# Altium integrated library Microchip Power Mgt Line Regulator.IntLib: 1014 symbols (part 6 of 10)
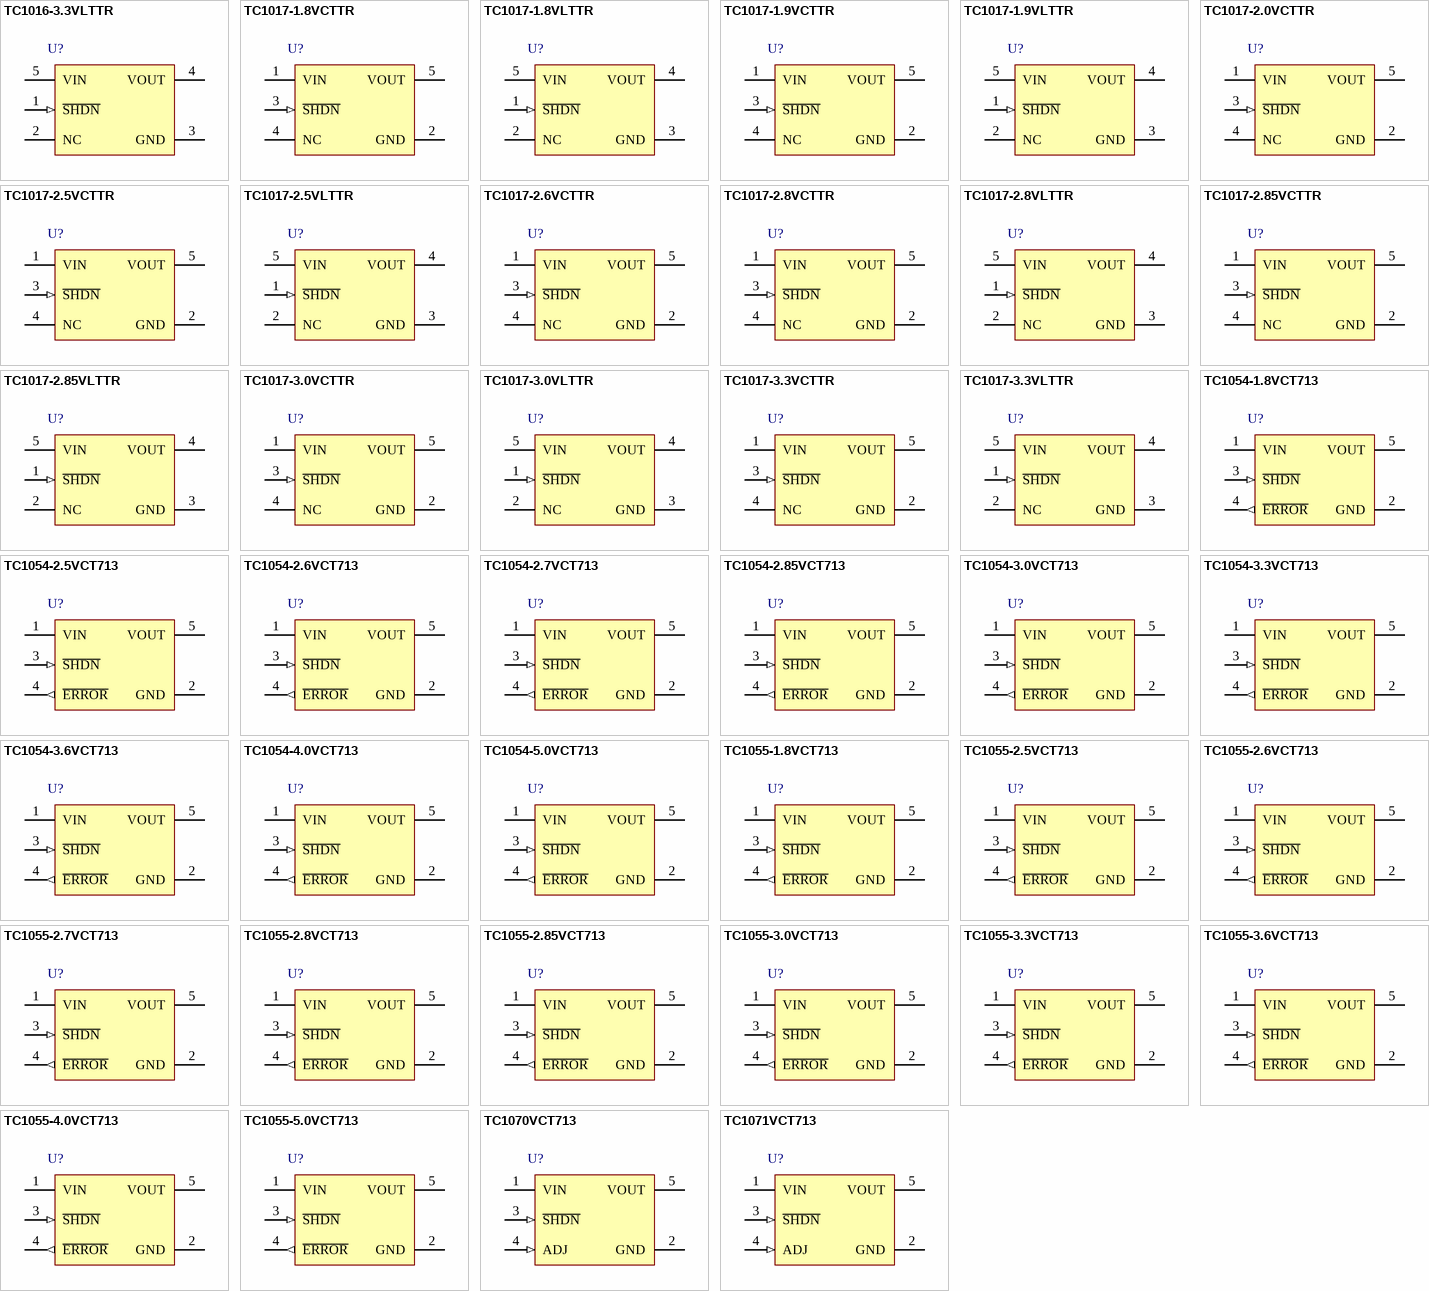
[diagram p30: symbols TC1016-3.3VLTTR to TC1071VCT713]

## TC1017-2.6VCTTR
designator U?
150 mA, Tiny CMOS LDO with Shutdown, 5-Pin SOT-23, Extended Temperature, Tape and Reel
footprint SOT-23-CT5_N (SOT23, 5-Leads, Body 2.9x1.6mm, Pitch 0.95mm, Lead Span 2.7mm, IPC Medium Density)
footprint SOT-23-CT5_L (SOT23, 5-Leads, Body 2.9x1.6mm, Pitch 0.95mm, Lead Span 2.7mm, IPC High Density)
footprint SOT-23-CT5_M (SOT23, 5-Leads, Body 2.9x1.6mm, Pitch 0.95mm, Lead Span 2.7mm, IPC Low Density)
pins: 1 VIN (power), 2 GND (power), 3 ~{SHDN} (in), 4 NC, 5 VOUT (power)

## TC1017-2.8VCTTR
designator U?
150 mA, Tiny CMOS LDO with Shutdown, 5-Pin SOT-23, Extended Temperature, Tape and Reel
footprint SOT-23-CT5_N (SOT23, 5-Leads, Body 2.9x1.6mm, Pitch 0.95mm, Lead Span 2.7mm, IPC Medium Density)
footprint SOT-23-CT5_L (SOT23, 5-Leads, Body 2.9x1.6mm, Pitch 0.95mm, Lead Span 2.7mm, IPC High Density)
footprint SOT-23-CT5_M (SOT23, 5-Leads, Body 2.9x1.6mm, Pitch 0.95mm, Lead Span 2.7mm, IPC Low Density)
pins: 1 VIN (power), 2 GND (power), 3 ~{SHDN} (in), 4 NC, 5 VOUT (power)

## TC1017-2.8VLTTR
designator U?
150 mA, Tiny CMOS LDO with Shutdown, 5-Pin SC-70, Extended Temperature, Tape and Reel
footprint SC70-LT5_N (SOT353, 5-Leads, Body 2x1.3mm, Pitch 0.65mm, Lead Span 2.1mm, IPC Medium Density)
footprint SC70-LT5_L (SOT353, 5-Leads, Body 2x1.3mm, Pitch 0.65mm, Lead Span 2.1mm, IPC High Density)
footprint SC70-LT5_M (SOT353, 5-Leads, Body 2x1.3mm, Pitch 0.65mm, Lead Span 2.1mm, IPC Low Density)
pins: 1 ~{SHDN} (in), 2 NC, 3 GND (power), 4 VOUT (power), 5 VIN (power)

## TC1017-2.85VCTTR
designator U?
150 mA, Tiny CMOS LDO with Shutdown, 5-Pin SOT-23, Extended Temperature, Tape and Reel
footprint SOT-23-CT5_N (SOT23, 5-Leads, Body 2.9x1.6mm, Pitch 0.95mm, Lead Span 2.7mm, IPC Medium Density)
footprint SOT-23-CT5_L (SOT23, 5-Leads, Body 2.9x1.6mm, Pitch 0.95mm, Lead Span 2.7mm, IPC High Density)
footprint SOT-23-CT5_M (SOT23, 5-Leads, Body 2.9x1.6mm, Pitch 0.95mm, Lead Span 2.7mm, IPC Low Density)
pins: 1 VIN (power), 2 GND (power), 3 ~{SHDN} (in), 4 NC, 5 VOUT (power)

## TC1017-2.85VLTTR
designator U?
150 mA, Tiny CMOS LDO with Shutdown, 5-Pin SC-70, Extended Temperature, Tape and Reel
footprint SC70-LT5_N (SOT353, 5-Leads, Body 2x1.3mm, Pitch 0.65mm, Lead Span 2.1mm, IPC Medium Density)
footprint SC70-LT5_L (SOT353, 5-Leads, Body 2x1.3mm, Pitch 0.65mm, Lead Span 2.1mm, IPC High Density)
footprint SC70-LT5_M (SOT353, 5-Leads, Body 2x1.3mm, Pitch 0.65mm, Lead Span 2.1mm, IPC Low Density)
pins: 1 ~{SHDN} (in), 2 NC, 3 GND (power), 4 VOUT (power), 5 VIN (power)

## TC1017-3.0VCTTR
designator U?
150 mA, Tiny CMOS LDO with Shutdown, 5-Pin SOT-23, Extended Temperature, Tape and Reel
footprint SOT-23-CT5_N (SOT23, 5-Leads, Body 2.9x1.6mm, Pitch 0.95mm, Lead Span 2.7mm, IPC Medium Density)
footprint SOT-23-CT5_L (SOT23, 5-Leads, Body 2.9x1.6mm, Pitch 0.95mm, Lead Span 2.7mm, IPC High Density)
footprint SOT-23-CT5_M (SOT23, 5-Leads, Body 2.9x1.6mm, Pitch 0.95mm, Lead Span 2.7mm, IPC Low Density)
pins: 1 VIN (power), 2 GND (power), 3 ~{SHDN} (in), 4 NC, 5 VOUT (power)

## TC1017-3.0VLTTR
designator U?
150 mA, Tiny CMOS LDO with Shutdown, 5-Pin SC-70, Extended Temperature, Tape and Reel
footprint SC70-LT5_N (SOT353, 5-Leads, Body 2x1.3mm, Pitch 0.65mm, Lead Span 2.1mm, IPC Medium Density)
footprint SC70-LT5_L (SOT353, 5-Leads, Body 2x1.3mm, Pitch 0.65mm, Lead Span 2.1mm, IPC High Density)
footprint SC70-LT5_M (SOT353, 5-Leads, Body 2x1.3mm, Pitch 0.65mm, Lead Span 2.1mm, IPC Low Density)
pins: 1 ~{SHDN} (in), 2 NC, 3 GND (power), 4 VOUT (power), 5 VIN (power)

## TC1017-3.3VCTTR
designator U?
150 mA, Tiny CMOS LDO with Shutdown, 5-Pin SOT-23, Extended Temperature, Tape and Reel
footprint SOT-23-CT5_N (SOT23, 5-Leads, Body 2.9x1.6mm, Pitch 0.95mm, Lead Span 2.7mm, IPC Medium Density)
footprint SOT-23-CT5_L (SOT23, 5-Leads, Body 2.9x1.6mm, Pitch 0.95mm, Lead Span 2.7mm, IPC High Density)
footprint SOT-23-CT5_M (SOT23, 5-Leads, Body 2.9x1.6mm, Pitch 0.95mm, Lead Span 2.7mm, IPC Low Density)
pins: 1 VIN (power), 2 GND (power), 3 ~{SHDN} (in), 4 NC, 5 VOUT (power)

## TC1017-3.3VLTTR
designator U?
150 mA, Tiny CMOS LDO with Shutdown, 5-Pin SC-70, Extended Temperature, Tape and Reel
footprint SC70-LT5_N (SOT353, 5-Leads, Body 2x1.3mm, Pitch 0.65mm, Lead Span 2.1mm, IPC Medium Density)
footprint SC70-LT5_L (SOT353, 5-Leads, Body 2x1.3mm, Pitch 0.65mm, Lead Span 2.1mm, IPC High Density)
footprint SC70-LT5_M (SOT353, 5-Leads, Body 2x1.3mm, Pitch 0.65mm, Lead Span 2.1mm, IPC Low Density)
pins: 1 ~{SHDN} (in), 2 NC, 3 GND (power), 4 VOUT (power), 5 VIN (power)

## TC1054-1.8VCT713
designator U?
50 mA, 100 mA and 150 mA CMOS LDOs with Shutdown and Active-Low Error Output, 5-Pin SOT-23, Extended Temperature, Tape and Reel
footprint SOT-23-CT5_N (SOT23, 5-Leads, Body 2.9x1.6mm, Pitch 0.95mm, Lead Span 2.7mm, IPC Medium Density)
footprint SOT-23-CT5_L (SOT23, 5-Leads, Body 2.9x1.6mm, Pitch 0.95mm, Lead Span 2.7mm, IPC High Density)
footprint SOT-23-CT5_M (SOT23, 5-Leads, Body 2.9x1.6mm, Pitch 0.95mm, Lead Span 2.7mm, IPC Low Density)
pins: 1 VIN (power), 2 GND (power), 3 ~{SHDN} (in), 4 ~{ERROR} (out), 5 VOUT (power)

## TC1054-2.5VCT713
designator U?
50 mA, 100 mA and 150 mA CMOS LDOs with Shutdown and Active-Low Error Output, 5-Pin SOT-23, Extended Temperature, Tape and Reel
footprint SOT-23-CT5_N (SOT23, 5-Leads, Body 2.9x1.6mm, Pitch 0.95mm, Lead Span 2.7mm, IPC Medium Density)
footprint SOT-23-CT5_L (SOT23, 5-Leads, Body 2.9x1.6mm, Pitch 0.95mm, Lead Span 2.7mm, IPC High Density)
footprint SOT-23-CT5_M (SOT23, 5-Leads, Body 2.9x1.6mm, Pitch 0.95mm, Lead Span 2.7mm, IPC Low Density)
pins: 1 VIN (power), 2 GND (power), 3 ~{SHDN} (in), 4 ~{ERROR} (out), 5 VOUT (power)

## TC1054-2.6VCT713
designator U?
50 mA, 100 mA and 150 mA CMOS LDOs with Shutdown and Active-Low Error Output, 5-Pin SOT-23, Extended Temperature, Tape and Reel
footprint SOT-23-CT5_N (SOT23, 5-Leads, Body 2.9x1.6mm, Pitch 0.95mm, Lead Span 2.7mm, IPC Medium Density)
footprint SOT-23-CT5_L (SOT23, 5-Leads, Body 2.9x1.6mm, Pitch 0.95mm, Lead Span 2.7mm, IPC High Density)
footprint SOT-23-CT5_M (SOT23, 5-Leads, Body 2.9x1.6mm, Pitch 0.95mm, Lead Span 2.7mm, IPC Low Density)
pins: 1 VIN (power), 2 GND (power), 3 ~{SHDN} (in), 4 ~{ERROR} (out), 5 VOUT (power)

## TC1054-2.7VCT713
designator U?
50 mA, 100 mA and 150 mA CMOS LDOs with Shutdown and Active-Low Error Output, 5-Pin SOT-23, Extended Temperature, Tape and Reel
footprint SOT-23-CT5_N (SOT23, 5-Leads, Body 2.9x1.6mm, Pitch 0.95mm, Lead Span 2.7mm, IPC Medium Density)
footprint SOT-23-CT5_L (SOT23, 5-Leads, Body 2.9x1.6mm, Pitch 0.95mm, Lead Span 2.7mm, IPC High Density)
footprint SOT-23-CT5_M (SOT23, 5-Leads, Body 2.9x1.6mm, Pitch 0.95mm, Lead Span 2.7mm, IPC Low Density)
pins: 1 VIN (power), 2 GND (power), 3 ~{SHDN} (in), 4 ~{ERROR} (out), 5 VOUT (power)

## TC1054-2.85VCT713
designator U?
50 mA, 100 mA and 150 mA CMOS LDOs with Shutdown and Active-Low Error Output, 5-Pin SOT-23, Extended Temperature, Tape and Reel
footprint SOT-23-CT5_N (SOT23, 5-Leads, Body 2.9x1.6mm, Pitch 0.95mm, Lead Span 2.7mm, IPC Medium Density)
footprint SOT-23-CT5_L (SOT23, 5-Leads, Body 2.9x1.6mm, Pitch 0.95mm, Lead Span 2.7mm, IPC High Density)
footprint SOT-23-CT5_M (SOT23, 5-Leads, Body 2.9x1.6mm, Pitch 0.95mm, Lead Span 2.7mm, IPC Low Density)
pins: 1 VIN (power), 2 GND (power), 3 ~{SHDN} (in), 4 ~{ERROR} (out), 5 VOUT (power)

## TC1054-3.0VCT713
designator U?
50 mA, 100 mA and 150 mA CMOS LDOs with Shutdown and Active-Low Error Output, 5-Pin SOT-23, Extended Temperature, Tape and Reel
footprint SOT-23-CT5_N (SOT23, 5-Leads, Body 2.9x1.6mm, Pitch 0.95mm, Lead Span 2.7mm, IPC Medium Density)
footprint SOT-23-CT5_L (SOT23, 5-Leads, Body 2.9x1.6mm, Pitch 0.95mm, Lead Span 2.7mm, IPC High Density)
footprint SOT-23-CT5_M (SOT23, 5-Leads, Body 2.9x1.6mm, Pitch 0.95mm, Lead Span 2.7mm, IPC Low Density)
pins: 1 VIN (power), 2 GND (power), 3 ~{SHDN} (in), 4 ~{ERROR} (out), 5 VOUT (power)

## TC1054-3.3VCT713
designator U?
50 mA, 100 mA and 150 mA CMOS LDOs with Shutdown and Active-Low Error Output, 5-Pin SOT-23, Extended Temperature, Tape and Reel
footprint SOT-23-CT5_N (SOT23, 5-Leads, Body 2.9x1.6mm, Pitch 0.95mm, Lead Span 2.7mm, IPC Medium Density)
footprint SOT-23-CT5_L (SOT23, 5-Leads, Body 2.9x1.6mm, Pitch 0.95mm, Lead Span 2.7mm, IPC High Density)
footprint SOT-23-CT5_M (SOT23, 5-Leads, Body 2.9x1.6mm, Pitch 0.95mm, Lead Span 2.7mm, IPC Low Density)
pins: 1 VIN (power), 2 GND (power), 3 ~{SHDN} (in), 4 ~{ERROR} (out), 5 VOUT (power)

## TC1054-3.6VCT713
designator U?
50 mA, 100 mA and 150 mA CMOS LDOs with Shutdown and Active-Low Error Output, 5-Pin SOT-23, Extended Temperature, Tape and Reel
footprint SOT-23-CT5_N (SOT23, 5-Leads, Body 2.9x1.6mm, Pitch 0.95mm, Lead Span 2.7mm, IPC Medium Density)
footprint SOT-23-CT5_L (SOT23, 5-Leads, Body 2.9x1.6mm, Pitch 0.95mm, Lead Span 2.7mm, IPC High Density)
footprint SOT-23-CT5_M (SOT23, 5-Leads, Body 2.9x1.6mm, Pitch 0.95mm, Lead Span 2.7mm, IPC Low Density)
pins: 1 VIN (power), 2 GND (power), 3 ~{SHDN} (in), 4 ~{ERROR} (out), 5 VOUT (power)

## TC1054-4.0VCT713
designator U?
50 mA, 100 mA and 150 mA CMOS LDOs with Shutdown and Active-Low Error Output, 5-Pin SOT-23, Extended Temperature, Tape and Reel
footprint SOT-23-CT5_N (SOT23, 5-Leads, Body 2.9x1.6mm, Pitch 0.95mm, Lead Span 2.7mm, IPC Medium Density)
footprint SOT-23-CT5_L (SOT23, 5-Leads, Body 2.9x1.6mm, Pitch 0.95mm, Lead Span 2.7mm, IPC High Density)
footprint SOT-23-CT5_M (SOT23, 5-Leads, Body 2.9x1.6mm, Pitch 0.95mm, Lead Span 2.7mm, IPC Low Density)
pins: 1 VIN (power), 2 GND (power), 3 ~{SHDN} (in), 4 ~{ERROR} (out), 5 VOUT (power)

## TC1054-5.0VCT713
designator U?
50 mA, 100 mA and 150 mA CMOS LDOs with Shutdown and Active-Low Error Output, 5-Pin SOT-23, Extended Temperature, Tape and Reel
footprint SOT-23-CT5_N (SOT23, 5-Leads, Body 2.9x1.6mm, Pitch 0.95mm, Lead Span 2.7mm, IPC Medium Density)
footprint SOT-23-CT5_L (SOT23, 5-Leads, Body 2.9x1.6mm, Pitch 0.95mm, Lead Span 2.7mm, IPC High Density)
footprint SOT-23-CT5_M (SOT23, 5-Leads, Body 2.9x1.6mm, Pitch 0.95mm, Lead Span 2.7mm, IPC Low Density)
pins: 1 VIN (power), 2 GND (power), 3 ~{SHDN} (in), 4 ~{ERROR} (out), 5 VOUT (power)

## TC1055-1.8VCT713
designator U?
50 mA, 100 mA and 150 mA CMOS LDOs with Shutdown and Active-Low Error Output, 5-Pin SOT-23, Extended Temperature, Tape and Reel
footprint SOT-23-CT5_N (SOT23, 5-Leads, Body 2.9x1.6mm, Pitch 0.95mm, Lead Span 2.7mm, IPC Medium Density)
footprint SOT-23-CT5_L (SOT23, 5-Leads, Body 2.9x1.6mm, Pitch 0.95mm, Lead Span 2.7mm, IPC High Density)
footprint SOT-23-CT5_M (SOT23, 5-Leads, Body 2.9x1.6mm, Pitch 0.95mm, Lead Span 2.7mm, IPC Low Density)
pins: 1 VIN (power), 2 GND (power), 3 ~{SHDN} (in), 4 ~{ERROR} (out), 5 VOUT (power)

## TC1055-2.5VCT713
designator U?
50 mA, 100 mA and 150 mA CMOS LDOs with Shutdown and Active-Low Error Output, 5-Pin SOT-23, Extended Temperature, Tape and Reel
footprint SOT-23-CT5_N (SOT23, 5-Leads, Body 2.9x1.6mm, Pitch 0.95mm, Lead Span 2.7mm, IPC Medium Density)
footprint SOT-23-CT5_L (SOT23, 5-Leads, Body 2.9x1.6mm, Pitch 0.95mm, Lead Span 2.7mm, IPC High Density)
footprint SOT-23-CT5_M (SOT23, 5-Leads, Body 2.9x1.6mm, Pitch 0.95mm, Lead Span 2.7mm, IPC Low Density)
pins: 1 VIN (power), 2 GND (power), 3 ~{SHDN} (in), 4 ~{ERROR} (out), 5 VOUT (power)

## TC1055-2.6VCT713
designator U?
50 mA, 100 mA and 150 mA CMOS LDOs with Shutdown and Active-Low Error Output, 5-Pin SOT-23, Extended Temperature, Tape and Reel
footprint SOT-23-CT5_N (SOT23, 5-Leads, Body 2.9x1.6mm, Pitch 0.95mm, Lead Span 2.7mm, IPC Medium Density)
footprint SOT-23-CT5_L (SOT23, 5-Leads, Body 2.9x1.6mm, Pitch 0.95mm, Lead Span 2.7mm, IPC High Density)
footprint SOT-23-CT5_M (SOT23, 5-Leads, Body 2.9x1.6mm, Pitch 0.95mm, Lead Span 2.7mm, IPC Low Density)
pins: 1 VIN (power), 2 GND (power), 3 ~{SHDN} (in), 4 ~{ERROR} (out), 5 VOUT (power)

## TC1055-2.7VCT713
designator U?
50 mA, 100 mA and 150 mA CMOS LDOs with Shutdown and Active-Low Error Output, 5-Pin SOT-23, Extended Temperature, Tape and Reel
footprint SOT-23-CT5_N (SOT23, 5-Leads, Body 2.9x1.6mm, Pitch 0.95mm, Lead Span 2.7mm, IPC Medium Density)
footprint SOT-23-CT5_L (SOT23, 5-Leads, Body 2.9x1.6mm, Pitch 0.95mm, Lead Span 2.7mm, IPC High Density)
footprint SOT-23-CT5_M (SOT23, 5-Leads, Body 2.9x1.6mm, Pitch 0.95mm, Lead Span 2.7mm, IPC Low Density)
pins: 1 VIN (power), 2 GND (power), 3 ~{SHDN} (in), 4 ~{ERROR} (out), 5 VOUT (power)

## TC1055-2.8VCT713
designator U?
50 mA, 100 mA and 150 mA CMOS LDOs with Shutdown and Active-Low Error Output, 5-Pin SOT-23, Extended Temperature, Tape and Reel
footprint SOT-23-CT5_N (SOT23, 5-Leads, Body 2.9x1.6mm, Pitch 0.95mm, Lead Span 2.7mm, IPC Medium Density)
footprint SOT-23-CT5_L (SOT23, 5-Leads, Body 2.9x1.6mm, Pitch 0.95mm, Lead Span 2.7mm, IPC High Density)
footprint SOT-23-CT5_M (SOT23, 5-Leads, Body 2.9x1.6mm, Pitch 0.95mm, Lead Span 2.7mm, IPC Low Density)
pins: 1 VIN (power), 2 GND (power), 3 ~{SHDN} (in), 4 ~{ERROR} (out), 5 VOUT (power)

## TC1055-2.85VCT713
designator U?
50 mA, 100 mA and 150 mA CMOS LDOs with Shutdown and Active-Low Error Output, 5-Pin SOT-23, Extended Temperature, Tape and Reel
footprint SOT-23-CT5_N (SOT23, 5-Leads, Body 2.9x1.6mm, Pitch 0.95mm, Lead Span 2.7mm, IPC Medium Density)
footprint SOT-23-CT5_L (SOT23, 5-Leads, Body 2.9x1.6mm, Pitch 0.95mm, Lead Span 2.7mm, IPC High Density)
footprint SOT-23-CT5_M (SOT23, 5-Leads, Body 2.9x1.6mm, Pitch 0.95mm, Lead Span 2.7mm, IPC Low Density)
pins: 1 VIN (power), 2 GND (power), 3 ~{SHDN} (in), 4 ~{ERROR} (out), 5 VOUT (power)

## TC1055-3.0VCT713
designator U?
50 mA, 100 mA and 150 mA CMOS LDOs with Shutdown and Active-Low Error Output, 5-Pin SOT-23, Extended Temperature, Tape and Reel
footprint SOT-23-CT5_N (SOT23, 5-Leads, Body 2.9x1.6mm, Pitch 0.95mm, Lead Span 2.7mm, IPC Medium Density)
footprint SOT-23-CT5_L (SOT23, 5-Leads, Body 2.9x1.6mm, Pitch 0.95mm, Lead Span 2.7mm, IPC High Density)
footprint SOT-23-CT5_M (SOT23, 5-Leads, Body 2.9x1.6mm, Pitch 0.95mm, Lead Span 2.7mm, IPC Low Density)
pins: 1 VIN (power), 2 GND (power), 3 ~{SHDN} (in), 4 ~{ERROR} (out), 5 VOUT (power)

## TC1055-3.3VCT713
designator U?
50 mA, 100 mA and 150 mA CMOS LDOs with Shutdown and Active-Low Error Output, 5-Pin SOT-23, Extended Temperature, Tape and Reel
footprint SOT-23-CT5_N (SOT23, 5-Leads, Body 2.9x1.6mm, Pitch 0.95mm, Lead Span 2.7mm, IPC Medium Density)
footprint SOT-23-CT5_L (SOT23, 5-Leads, Body 2.9x1.6mm, Pitch 0.95mm, Lead Span 2.7mm, IPC High Density)
footprint SOT-23-CT5_M (SOT23, 5-Leads, Body 2.9x1.6mm, Pitch 0.95mm, Lead Span 2.7mm, IPC Low Density)
pins: 1 VIN (power), 2 GND (power), 3 ~{SHDN} (in), 4 ~{ERROR} (out), 5 VOUT (power)

## TC1055-3.6VCT713
designator U?
50 mA, 100 mA and 150 mA CMOS LDOs with Shutdown and Active-Low Error Output, 5-Pin SOT-23, Extended Temperature, Tape and Reel
footprint SOT-23-CT5_N (SOT23, 5-Leads, Body 2.9x1.6mm, Pitch 0.95mm, Lead Span 2.7mm, IPC Medium Density)
footprint SOT-23-CT5_L (SOT23, 5-Leads, Body 2.9x1.6mm, Pitch 0.95mm, Lead Span 2.7mm, IPC High Density)
footprint SOT-23-CT5_M (SOT23, 5-Leads, Body 2.9x1.6mm, Pitch 0.95mm, Lead Span 2.7mm, IPC Low Density)
pins: 1 VIN (power), 2 GND (power), 3 ~{SHDN} (in), 4 ~{ERROR} (out), 5 VOUT (power)

## TC1055-4.0VCT713
designator U?
50 mA, 100 mA and 150 mA CMOS LDOs with Shutdown and Active-Low Error Output, 5-Pin SOT-23, Extended Temperature, Tape and Reel
footprint SOT-23-CT5_N (SOT23, 5-Leads, Body 2.9x1.6mm, Pitch 0.95mm, Lead Span 2.7mm, IPC Medium Density)
footprint SOT-23-CT5_L (SOT23, 5-Leads, Body 2.9x1.6mm, Pitch 0.95mm, Lead Span 2.7mm, IPC High Density)
footprint SOT-23-CT5_M (SOT23, 5-Leads, Body 2.9x1.6mm, Pitch 0.95mm, Lead Span 2.7mm, IPC Low Density)
pins: 1 VIN (power), 2 GND (power), 3 ~{SHDN} (in), 4 ~{ERROR} (out), 5 VOUT (power)

## TC1055-5.0VCT713
designator U?
50 mA, 100 mA and 150 mA CMOS LDOs with Shutdown and Active-Low Error Output, 5-Pin SOT-23, Extended Temperature, Tape and Reel
footprint SOT-23-CT5_N (SOT23, 5-Leads, Body 2.9x1.6mm, Pitch 0.95mm, Lead Span 2.7mm, IPC Medium Density)
footprint SOT-23-CT5_L (SOT23, 5-Leads, Body 2.9x1.6mm, Pitch 0.95mm, Lead Span 2.7mm, IPC High Density)
footprint SOT-23-CT5_M (SOT23, 5-Leads, Body 2.9x1.6mm, Pitch 0.95mm, Lead Span 2.7mm, IPC Low Density)
pins: 1 VIN (power), 2 GND (power), 3 ~{SHDN} (in), 4 ~{ERROR} (out), 5 VOUT (power)

## TC1070VCT713
designator U?
50mA, 100mA and 150mA Adjustable CMOS LDOs with Shutdown, 5-Pin SOT-23, Extended Temperature, Tape and Reel
footprint SOT-23-CT5_N (SOT23, 5-Leads, Body 2.9x1.6mm, Pitch 0.95mm, Lead Span 2.7mm, IPC Medium Density)
footprint SOT-23-CT5_L (SOT23, 5-Leads, Body 2.9x1.6mm, Pitch 0.95mm, Lead Span 2.7mm, IPC High Density)
footprint SOT-23-CT5_M (SOT23, 5-Leads, Body 2.9x1.6mm, Pitch 0.95mm, Lead Span 2.7mm, IPC Low Density)
pins: 1 VIN (power), 2 GND (power), 3 ~{SHDN} (in), 4 ADJ (in), 5 VOUT (power)

## TC1071VCT713
designator U?
50mA, 100mA and 150mA Adjustable CMOS LDOs with Shutdown, 5-Pin SOT-23, Extended Temperature, Tape and Reel
footprint SOT-23-CT5_N (SOT23, 5-Leads, Body 2.9x1.6mm, Pitch 0.95mm, Lead Span 2.7mm, IPC Medium Density)
footprint SOT-23-CT5_L (SOT23, 5-Leads, Body 2.9x1.6mm, Pitch 0.95mm, Lead Span 2.7mm, IPC High Density)
footprint SOT-23-CT5_M (SOT23, 5-Leads, Body 2.9x1.6mm, Pitch 0.95mm, Lead Span 2.7mm, IPC Low Density)
pins: 1 VIN (power), 2 GND (power), 3 ~{SHDN} (in), 4 ADJ (in), 5 VOUT (power)

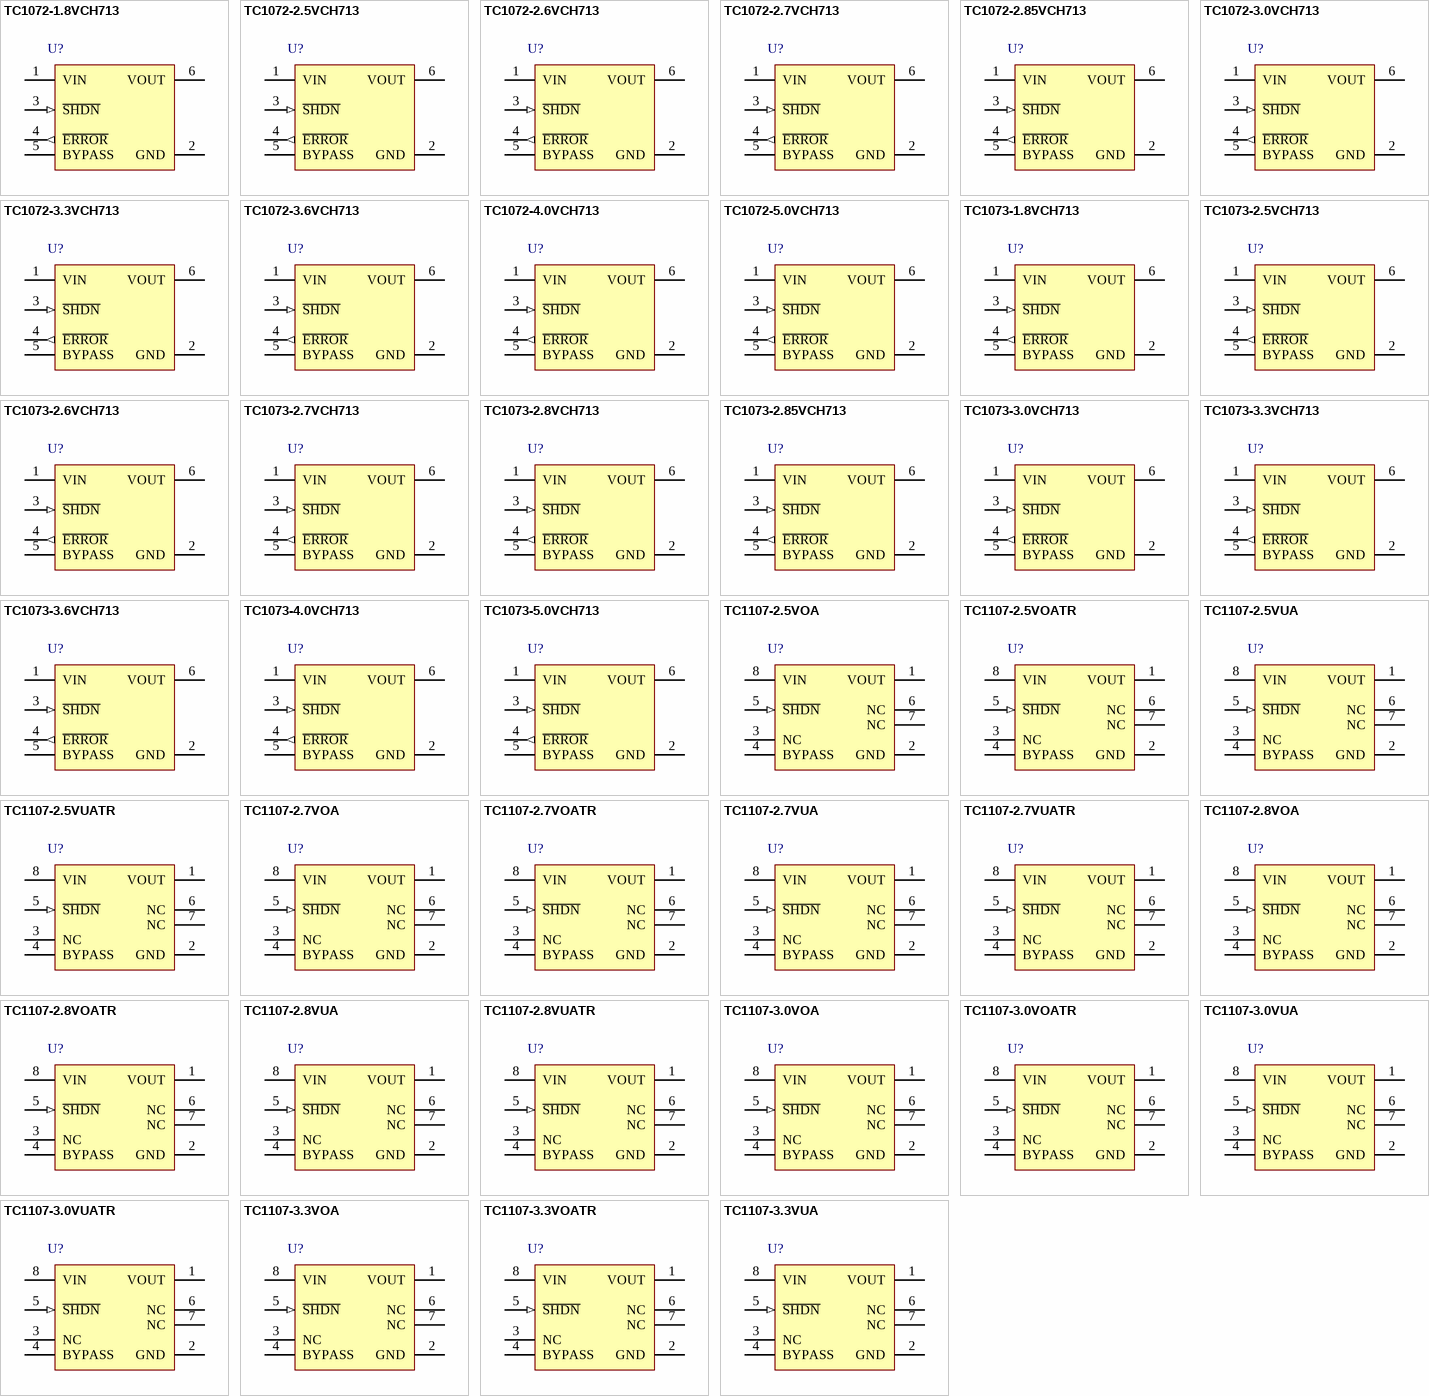
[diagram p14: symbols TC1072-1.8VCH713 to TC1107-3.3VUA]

## TC1072-1.8VCH713
designator U?
50mA and 100mA CMOS LDOs with Shutdown, Active-Low Error Output and VREF Bypass, 6-Pin SOT-23, Extended Temperature, Tape and Reel
footprint SOT-23-CH6_N (SOT23, 6-Leads, Body 2.9x1.6mm, Pitch 0.95mm, Lead Span 2.7mm, IPC Medium Density)
footprint SOT-23-CH6_L (SOT23, 6-Leads, Body 2.9x1.6mm, Pitch 0.95mm, Lead Span 2.7mm, IPC High Density)
footprint SOT-23-CH6_M (SOT23, 6-Leads, Body 2.9x1.6mm, Pitch 0.95mm, Lead Span 2.7mm, IPC Low Density)
pins: 1 VIN (power), 2 GND (power), 3 ~{SHDN} (in), 4 ~{ERROR} (out), 5 BYPASS, 6 VOUT (power)

## TC1072-2.5VCH713
designator U?
50mA and 100mA CMOS LDOs with Shutdown, Active-Low Error Output and VREF Bypass, 6-Pin SOT-23, Extended Temperature, Tape and Reel
footprint SOT-23-CH6_N (SOT23, 6-Leads, Body 2.9x1.6mm, Pitch 0.95mm, Lead Span 2.7mm, IPC Medium Density)
footprint SOT-23-CH6_L (SOT23, 6-Leads, Body 2.9x1.6mm, Pitch 0.95mm, Lead Span 2.7mm, IPC High Density)
footprint SOT-23-CH6_M (SOT23, 6-Leads, Body 2.9x1.6mm, Pitch 0.95mm, Lead Span 2.7mm, IPC Low Density)
pins: 1 VIN (power), 2 GND (power), 3 ~{SHDN} (in), 4 ~{ERROR} (out), 5 BYPASS, 6 VOUT (power)

## TC1072-2.6VCH713
designator U?
50mA and 100mA CMOS LDOs with Shutdown, Active-Low Error Output and VREF Bypass, 6-Pin SOT-23, Extended Temperature, Tape and Reel
footprint SOT-23-CH6_N (SOT23, 6-Leads, Body 2.9x1.6mm, Pitch 0.95mm, Lead Span 2.7mm, IPC Medium Density)
footprint SOT-23-CH6_L (SOT23, 6-Leads, Body 2.9x1.6mm, Pitch 0.95mm, Lead Span 2.7mm, IPC High Density)
footprint SOT-23-CH6_M (SOT23, 6-Leads, Body 2.9x1.6mm, Pitch 0.95mm, Lead Span 2.7mm, IPC Low Density)
pins: 1 VIN (power), 2 GND (power), 3 ~{SHDN} (in), 4 ~{ERROR} (out), 5 BYPASS, 6 VOUT (power)

## TC1072-2.7VCH713
designator U?
50mA and 100mA CMOS LDOs with Shutdown, Active-Low Error Output and VREF Bypass, 6-Pin SOT-23, Extended Temperature, Tape and Reel
footprint SOT-23-CH6_N (SOT23, 6-Leads, Body 2.9x1.6mm, Pitch 0.95mm, Lead Span 2.7mm, IPC Medium Density)
footprint SOT-23-CH6_L (SOT23, 6-Leads, Body 2.9x1.6mm, Pitch 0.95mm, Lead Span 2.7mm, IPC High Density)
footprint SOT-23-CH6_M (SOT23, 6-Leads, Body 2.9x1.6mm, Pitch 0.95mm, Lead Span 2.7mm, IPC Low Density)
pins: 1 VIN (power), 2 GND (power), 3 ~{SHDN} (in), 4 ~{ERROR} (out), 5 BYPASS, 6 VOUT (power)

## TC1072-2.85VCH713
designator U?
50mA and 100mA CMOS LDOs with Shutdown, Active-Low Error Output and VREF Bypass, 6-Pin SOT-23, Extended Temperature, Tape and Reel
footprint SOT-23-CH6_N (SOT23, 6-Leads, Body 2.9x1.6mm, Pitch 0.95mm, Lead Span 2.7mm, IPC Medium Density)
footprint SOT-23-CH6_L (SOT23, 6-Leads, Body 2.9x1.6mm, Pitch 0.95mm, Lead Span 2.7mm, IPC High Density)
footprint SOT-23-CH6_M (SOT23, 6-Leads, Body 2.9x1.6mm, Pitch 0.95mm, Lead Span 2.7mm, IPC Low Density)
pins: 1 VIN (power), 2 GND (power), 3 ~{SHDN} (in), 4 ~{ERROR} (out), 5 BYPASS, 6 VOUT (power)

## TC1072-3.0VCH713
designator U?
50mA and 100mA CMOS LDOs with Shutdown, Active-Low Error Output and VREF Bypass, 6-Pin SOT-23, Extended Temperature, Tape and Reel
footprint SOT-23-CH6_N (SOT23, 6-Leads, Body 2.9x1.6mm, Pitch 0.95mm, Lead Span 2.7mm, IPC Medium Density)
footprint SOT-23-CH6_L (SOT23, 6-Leads, Body 2.9x1.6mm, Pitch 0.95mm, Lead Span 2.7mm, IPC High Density)
footprint SOT-23-CH6_M (SOT23, 6-Leads, Body 2.9x1.6mm, Pitch 0.95mm, Lead Span 2.7mm, IPC Low Density)
pins: 1 VIN (power), 2 GND (power), 3 ~{SHDN} (in), 4 ~{ERROR} (out), 5 BYPASS, 6 VOUT (power)

## TC1072-3.3VCH713
designator U?
50mA and 100mA CMOS LDOs with Shutdown, Active-Low Error Output and VREF Bypass, 6-Pin SOT-23, Extended Temperature, Tape and Reel
footprint SOT-23-CH6_N (SOT23, 6-Leads, Body 2.9x1.6mm, Pitch 0.95mm, Lead Span 2.7mm, IPC Medium Density)
footprint SOT-23-CH6_L (SOT23, 6-Leads, Body 2.9x1.6mm, Pitch 0.95mm, Lead Span 2.7mm, IPC High Density)
footprint SOT-23-CH6_M (SOT23, 6-Leads, Body 2.9x1.6mm, Pitch 0.95mm, Lead Span 2.7mm, IPC Low Density)
pins: 1 VIN (power), 2 GND (power), 3 ~{SHDN} (in), 4 ~{ERROR} (out), 5 BYPASS, 6 VOUT (power)

## TC1072-3.6VCH713
designator U?
50mA and 100mA CMOS LDOs with Shutdown, Active-Low Error Output and VREF Bypass, 6-Pin SOT-23, Extended Temperature, Tape and Reel
footprint SOT-23-CH6_N (SOT23, 6-Leads, Body 2.9x1.6mm, Pitch 0.95mm, Lead Span 2.7mm, IPC Medium Density)
footprint SOT-23-CH6_L (SOT23, 6-Leads, Body 2.9x1.6mm, Pitch 0.95mm, Lead Span 2.7mm, IPC High Density)
footprint SOT-23-CH6_M (SOT23, 6-Leads, Body 2.9x1.6mm, Pitch 0.95mm, Lead Span 2.7mm, IPC Low Density)
pins: 1 VIN (power), 2 GND (power), 3 ~{SHDN} (in), 4 ~{ERROR} (out), 5 BYPASS, 6 VOUT (power)

## TC1072-4.0VCH713
designator U?
50mA and 100mA CMOS LDOs with Shutdown, Active-Low Error Output and VREF Bypass, 6-Pin SOT-23, Extended Temperature, Tape and Reel
footprint SOT-23-CH6_N (SOT23, 6-Leads, Body 2.9x1.6mm, Pitch 0.95mm, Lead Span 2.7mm, IPC Medium Density)
footprint SOT-23-CH6_L (SOT23, 6-Leads, Body 2.9x1.6mm, Pitch 0.95mm, Lead Span 2.7mm, IPC High Density)
footprint SOT-23-CH6_M (SOT23, 6-Leads, Body 2.9x1.6mm, Pitch 0.95mm, Lead Span 2.7mm, IPC Low Density)
pins: 1 VIN (power), 2 GND (power), 3 ~{SHDN} (in), 4 ~{ERROR} (out), 5 BYPASS, 6 VOUT (power)

## TC1072-5.0VCH713
designator U?
50mA and 100mA CMOS LDOs with Shutdown, Active-Low Error Output and VREF Bypass, 6-Pin SOT-23, Extended Temperature, Tape and Reel
footprint SOT-23-CH6_N (SOT23, 6-Leads, Body 2.9x1.6mm, Pitch 0.95mm, Lead Span 2.7mm, IPC Medium Density)
footprint SOT-23-CH6_L (SOT23, 6-Leads, Body 2.9x1.6mm, Pitch 0.95mm, Lead Span 2.7mm, IPC High Density)
footprint SOT-23-CH6_M (SOT23, 6-Leads, Body 2.9x1.6mm, Pitch 0.95mm, Lead Span 2.7mm, IPC Low Density)
pins: 1 VIN (power), 2 GND (power), 3 ~{SHDN} (in), 4 ~{ERROR} (out), 5 BYPASS, 6 VOUT (power)

## TC1073-1.8VCH713
designator U?
50mA and 100mA CMOS LDOs with Shutdown, Active-Low Error Output and VREF Bypass, 6-Pin SOT-23, Extended Temperature, Tape and Reel
footprint SOT-23-CH6_N (SOT23, 6-Leads, Body 2.9x1.6mm, Pitch 0.95mm, Lead Span 2.7mm, IPC Medium Density)
footprint SOT-23-CH6_L (SOT23, 6-Leads, Body 2.9x1.6mm, Pitch 0.95mm, Lead Span 2.7mm, IPC High Density)
footprint SOT-23-CH6_M (SOT23, 6-Leads, Body 2.9x1.6mm, Pitch 0.95mm, Lead Span 2.7mm, IPC Low Density)
pins: 1 VIN (power), 2 GND (power), 3 ~{SHDN} (in), 4 ~{ERROR} (out), 5 BYPASS, 6 VOUT (power)

## TC1073-2.5VCH713
designator U?
50mA and 100mA CMOS LDOs with Shutdown, Active-Low Error Output and VREF Bypass, 6-Pin SOT-23, Extended Temperature, Tape and Reel
footprint SOT-23-CH6_N (SOT23, 6-Leads, Body 2.9x1.6mm, Pitch 0.95mm, Lead Span 2.7mm, IPC Medium Density)
footprint SOT-23-CH6_L (SOT23, 6-Leads, Body 2.9x1.6mm, Pitch 0.95mm, Lead Span 2.7mm, IPC High Density)
footprint SOT-23-CH6_M (SOT23, 6-Leads, Body 2.9x1.6mm, Pitch 0.95mm, Lead Span 2.7mm, IPC Low Density)
pins: 1 VIN (power), 2 GND (power), 3 ~{SHDN} (in), 4 ~{ERROR} (out), 5 BYPASS, 6 VOUT (power)

## TC1073-2.6VCH713
designator U?
50mA and 100mA CMOS LDOs with Shutdown, Active-Low Error Output and VREF Bypass, 6-Pin SOT-23, Extended Temperature, Tape and Reel
footprint SOT-23-CH6_N (SOT23, 6-Leads, Body 2.9x1.6mm, Pitch 0.95mm, Lead Span 2.7mm, IPC Medium Density)
footprint SOT-23-CH6_L (SOT23, 6-Leads, Body 2.9x1.6mm, Pitch 0.95mm, Lead Span 2.7mm, IPC High Density)
footprint SOT-23-CH6_M (SOT23, 6-Leads, Body 2.9x1.6mm, Pitch 0.95mm, Lead Span 2.7mm, IPC Low Density)
pins: 1 VIN (power), 2 GND (power), 3 ~{SHDN} (in), 4 ~{ERROR} (out), 5 BYPASS, 6 VOUT (power)

## TC1073-2.7VCH713
designator U?
50mA and 100mA CMOS LDOs with Shutdown, Active-Low Error Output and VREF Bypass, 6-Pin SOT-23, Extended Temperature, Tape and Reel
footprint SOT-23-CH6_N (SOT23, 6-Leads, Body 2.9x1.6mm, Pitch 0.95mm, Lead Span 2.7mm, IPC Medium Density)
footprint SOT-23-CH6_L (SOT23, 6-Leads, Body 2.9x1.6mm, Pitch 0.95mm, Lead Span 2.7mm, IPC High Density)
footprint SOT-23-CH6_M (SOT23, 6-Leads, Body 2.9x1.6mm, Pitch 0.95mm, Lead Span 2.7mm, IPC Low Density)
pins: 1 VIN (power), 2 GND (power), 3 ~{SHDN} (in), 4 ~{ERROR} (out), 5 BYPASS, 6 VOUT (power)

## TC1073-2.8VCH713
designator U?
50mA and 100mA CMOS LDOs with Shutdown, Active-Low Error Output and VREF Bypass, 6-Pin SOT-23, Extended Temperature, Tape and Reel
footprint SOT-23-CH6_N (SOT23, 6-Leads, Body 2.9x1.6mm, Pitch 0.95mm, Lead Span 2.7mm, IPC Medium Density)
footprint SOT-23-CH6_L (SOT23, 6-Leads, Body 2.9x1.6mm, Pitch 0.95mm, Lead Span 2.7mm, IPC High Density)
footprint SOT-23-CH6_M (SOT23, 6-Leads, Body 2.9x1.6mm, Pitch 0.95mm, Lead Span 2.7mm, IPC Low Density)
pins: 1 VIN (power), 2 GND (power), 3 ~{SHDN} (in), 4 ~{ERROR} (out), 5 BYPASS, 6 VOUT (power)

## TC1073-2.85VCH713
designator U?
50mA and 100mA CMOS LDOs with Shutdown, Active-Low Error Output and VREF Bypass, 6-Pin SOT-23, Extended Temperature, Tape and Reel
footprint SOT-23-CH6_N (SOT23, 6-Leads, Body 2.9x1.6mm, Pitch 0.95mm, Lead Span 2.7mm, IPC Medium Density)
footprint SOT-23-CH6_L (SOT23, 6-Leads, Body 2.9x1.6mm, Pitch 0.95mm, Lead Span 2.7mm, IPC High Density)
footprint SOT-23-CH6_M (SOT23, 6-Leads, Body 2.9x1.6mm, Pitch 0.95mm, Lead Span 2.7mm, IPC Low Density)
pins: 1 VIN (power), 2 GND (power), 3 ~{SHDN} (in), 4 ~{ERROR} (out), 5 BYPASS, 6 VOUT (power)

## TC1073-3.0VCH713
designator U?
50mA and 100mA CMOS LDOs with Shutdown, Active-Low Error Output and VREF Bypass, 6-Pin SOT-23, Extended Temperature, Tape and Reel
footprint SOT-23-CH6_N (SOT23, 6-Leads, Body 2.9x1.6mm, Pitch 0.95mm, Lead Span 2.7mm, IPC Medium Density)
footprint SOT-23-CH6_L (SOT23, 6-Leads, Body 2.9x1.6mm, Pitch 0.95mm, Lead Span 2.7mm, IPC High Density)
footprint SOT-23-CH6_M (SOT23, 6-Leads, Body 2.9x1.6mm, Pitch 0.95mm, Lead Span 2.7mm, IPC Low Density)
pins: 1 VIN (power), 2 GND (power), 3 ~{SHDN} (in), 4 ~{ERROR} (out), 5 BYPASS, 6 VOUT (power)

## TC1073-3.3VCH713
designator U?
50mA and 100mA CMOS LDOs with Shutdown, Active-Low Error Output and VREF Bypass, 6-Pin SOT-23, Extended Temperature, Tape and Reel
footprint SOT-23-CH6_N (SOT23, 6-Leads, Body 2.9x1.6mm, Pitch 0.95mm, Lead Span 2.7mm, IPC Medium Density)
footprint SOT-23-CH6_L (SOT23, 6-Leads, Body 2.9x1.6mm, Pitch 0.95mm, Lead Span 2.7mm, IPC High Density)
footprint SOT-23-CH6_M (SOT23, 6-Leads, Body 2.9x1.6mm, Pitch 0.95mm, Lead Span 2.7mm, IPC Low Density)
pins: 1 VIN (power), 2 GND (power), 3 ~{SHDN} (in), 4 ~{ERROR} (out), 5 BYPASS, 6 VOUT (power)

## TC1073-3.6VCH713
designator U?
50mA and 100mA CMOS LDOs with Shutdown, Active-Low Error Output and VREF Bypass, 6-Pin SOT-23, Extended Temperature, Tape and Reel
footprint SOT-23-CH6_N (SOT23, 6-Leads, Body 2.9x1.6mm, Pitch 0.95mm, Lead Span 2.7mm, IPC Medium Density)
footprint SOT-23-CH6_L (SOT23, 6-Leads, Body 2.9x1.6mm, Pitch 0.95mm, Lead Span 2.7mm, IPC High Density)
footprint SOT-23-CH6_M (SOT23, 6-Leads, Body 2.9x1.6mm, Pitch 0.95mm, Lead Span 2.7mm, IPC Low Density)
pins: 1 VIN (power), 2 GND (power), 3 ~{SHDN} (in), 4 ~{ERROR} (out), 5 BYPASS, 6 VOUT (power)

## TC1073-4.0VCH713
designator U?
50mA and 100mA CMOS LDOs with Shutdown, Active-Low Error Output and VREF Bypass, 6-Pin SOT-23, Extended Temperature, Tape and Reel
footprint SOT-23-CH6_N (SOT23, 6-Leads, Body 2.9x1.6mm, Pitch 0.95mm, Lead Span 2.7mm, IPC Medium Density)
footprint SOT-23-CH6_L (SOT23, 6-Leads, Body 2.9x1.6mm, Pitch 0.95mm, Lead Span 2.7mm, IPC High Density)
footprint SOT-23-CH6_M (SOT23, 6-Leads, Body 2.9x1.6mm, Pitch 0.95mm, Lead Span 2.7mm, IPC Low Density)
pins: 1 VIN (power), 2 GND (power), 3 ~{SHDN} (in), 4 ~{ERROR} (out), 5 BYPASS, 6 VOUT (power)

## TC1073-5.0VCH713
designator U?
50mA and 100mA CMOS LDOs with Shutdown, Active-Low Error Output and VREF Bypass, 6-Pin SOT-23, Extended Temperature, Tape and Reel
footprint SOT-23-CH6_N (SOT23, 6-Leads, Body 2.9x1.6mm, Pitch 0.95mm, Lead Span 2.7mm, IPC Medium Density)
footprint SOT-23-CH6_L (SOT23, 6-Leads, Body 2.9x1.6mm, Pitch 0.95mm, Lead Span 2.7mm, IPC High Density)
footprint SOT-23-CH6_M (SOT23, 6-Leads, Body 2.9x1.6mm, Pitch 0.95mm, Lead Span 2.7mm, IPC Low Density)
pins: 1 VIN (power), 2 GND (power), 3 ~{SHDN} (in), 4 ~{ERROR} (out), 5 BYPASS, 6 VOUT (power)

## TC1107-2.5VOA
designator U?
300mA CMOS LDO with Shutdown and VREF Bypass, 8-Pin SOIC 150mil, Extended Temperature
footprint SOIC-OA8_N (SOIC, 8-Leads, Body 4.9x3.9mm, Pitch 1.27mm, IPC Medium Density)
footprint SOIC-OA8_L (SOIC, 8-Leads, Body 4.9x3.9mm, Pitch 1.27mm, IPC High Density)
footprint SOIC-OA8_M (SOIC, 8-Leads, Body 4.9x3.9mm, Pitch 1.27mm, IPC Low Density)
pins: 1 VOUT (power), 2 GND (power), 3 NC, 4 BYPASS, 5 ~{SHDN} (in), 6 NC, 7 NC, 8 VIN (power)

## TC1107-2.5VOATR
designator U?
300mA CMOS LDO with Shutdown and VREF Bypass, 8-Pin SOIC 150mil, Extended Temperature, Tape and Reel
footprint SOIC-OA8_N (SOIC, 8-Leads, Body 4.9x3.9mm, Pitch 1.27mm, IPC Medium Density)
footprint SOIC-OA8_L (SOIC, 8-Leads, Body 4.9x3.9mm, Pitch 1.27mm, IPC High Density)
footprint SOIC-OA8_M (SOIC, 8-Leads, Body 4.9x3.9mm, Pitch 1.27mm, IPC Low Density)
pins: 1 VOUT (power), 2 GND (power), 3 NC, 4 BYPASS, 5 ~{SHDN} (in), 6 NC, 7 NC, 8 VIN (power)

## TC1107-2.5VUA
designator U?
300mA CMOS LDO with Shutdown and VREF Bypass, 8-Pin MSOP, Extended Temperature
footprint MSOP-UA8_N (TSOP, 8-Leads, Body 3x3mm, Pitch 0.65mm, IPC Medium Density)
footprint MSOP-UA8_L (TSOP, 8-Leads, Body 3x3mm, Pitch 0.65mm, IPC High Density)
footprint MSOP-UA8_M (TSOP, 8-Leads, Body 3x3mm, Pitch 0.65mm, IPC Low Density)
pins: 1 VOUT (power), 2 GND (power), 3 NC, 4 BYPASS, 5 ~{SHDN} (in), 6 NC, 7 NC, 8 VIN (power)

## TC1107-2.5VUATR
designator U?
300mA CMOS LDO with Shutdown and VREF Bypass, 8-Pin MSOP, Extended Temperature, Tape and Reel
footprint MSOP-UA8_N (TSOP, 8-Leads, Body 3x3mm, Pitch 0.65mm, IPC Medium Density)
footprint MSOP-UA8_L (TSOP, 8-Leads, Body 3x3mm, Pitch 0.65mm, IPC High Density)
footprint MSOP-UA8_M (TSOP, 8-Leads, Body 3x3mm, Pitch 0.65mm, IPC Low Density)
pins: 1 VOUT (power), 2 GND (power), 3 NC, 4 BYPASS, 5 ~{SHDN} (in), 6 NC, 7 NC, 8 VIN (power)

## TC1107-2.7VOA
designator U?
300mA CMOS LDO with Shutdown and VREF Bypass, 8-Pin SOIC 150mil, Extended Temperature
footprint SOIC-OA8_N (SOIC, 8-Leads, Body 4.9x3.9mm, Pitch 1.27mm, IPC Medium Density)
footprint SOIC-OA8_L (SOIC, 8-Leads, Body 4.9x3.9mm, Pitch 1.27mm, IPC High Density)
footprint SOIC-OA8_M (SOIC, 8-Leads, Body 4.9x3.9mm, Pitch 1.27mm, IPC Low Density)
pins: 1 VOUT (power), 2 GND (power), 3 NC, 4 BYPASS, 5 ~{SHDN} (in), 6 NC, 7 NC, 8 VIN (power)

## TC1107-2.7VOATR
designator U?
300mA CMOS LDO with Shutdown and VREF Bypass, 8-Pin SOIC 150mil, Extended Temperature, Tape and Reel
footprint SOIC-OA8_N (SOIC, 8-Leads, Body 4.9x3.9mm, Pitch 1.27mm, IPC Medium Density)
footprint SOIC-OA8_L (SOIC, 8-Leads, Body 4.9x3.9mm, Pitch 1.27mm, IPC High Density)
footprint SOIC-OA8_M (SOIC, 8-Leads, Body 4.9x3.9mm, Pitch 1.27mm, IPC Low Density)
pins: 1 VOUT (power), 2 GND (power), 3 NC, 4 BYPASS, 5 ~{SHDN} (in), 6 NC, 7 NC, 8 VIN (power)

## TC1107-2.7VUA
designator U?
300mA CMOS LDO with Shutdown and VREF Bypass, 8-Pin MSOP, Extended Temperature
footprint MSOP-UA8_N (TSOP, 8-Leads, Body 3x3mm, Pitch 0.65mm, IPC Medium Density)
footprint MSOP-UA8_L (TSOP, 8-Leads, Body 3x3mm, Pitch 0.65mm, IPC High Density)
footprint MSOP-UA8_M (TSOP, 8-Leads, Body 3x3mm, Pitch 0.65mm, IPC Low Density)
pins: 1 VOUT (power), 2 GND (power), 3 NC, 4 BYPASS, 5 ~{SHDN} (in), 6 NC, 7 NC, 8 VIN (power)

## TC1107-2.7VUATR
designator U?
300mA CMOS LDO with Shutdown and VREF Bypass, 8-Pin MSOP, Extended Temperature, Tape and Reel
footprint MSOP-UA8_N (TSOP, 8-Leads, Body 3x3mm, Pitch 0.65mm, IPC Medium Density)
footprint MSOP-UA8_L (TSOP, 8-Leads, Body 3x3mm, Pitch 0.65mm, IPC High Density)
footprint MSOP-UA8_M (TSOP, 8-Leads, Body 3x3mm, Pitch 0.65mm, IPC Low Density)
pins: 1 VOUT (power), 2 GND (power), 3 NC, 4 BYPASS, 5 ~{SHDN} (in), 6 NC, 7 NC, 8 VIN (power)

## TC1107-2.8VOA
designator U?
300mA CMOS LDO with Shutdown and VREF Bypass, 8-Pin SOIC 150mil, Extended Temperature
footprint SOIC-OA8_N (SOIC, 8-Leads, Body 4.9x3.9mm, Pitch 1.27mm, IPC Medium Density)
footprint SOIC-OA8_L (SOIC, 8-Leads, Body 4.9x3.9mm, Pitch 1.27mm, IPC High Density)
footprint SOIC-OA8_M (SOIC, 8-Leads, Body 4.9x3.9mm, Pitch 1.27mm, IPC Low Density)
pins: 1 VOUT (power), 2 GND (power), 3 NC, 4 BYPASS, 5 ~{SHDN} (in), 6 NC, 7 NC, 8 VIN (power)

## TC1107-2.8VOATR
designator U?
300mA CMOS LDO with Shutdown and VREF Bypass, 8-Pin SOIC 150mil, Extended Temperature, Tape and Reel
footprint SOIC-OA8_N (SOIC, 8-Leads, Body 4.9x3.9mm, Pitch 1.27mm, IPC Medium Density)
footprint SOIC-OA8_L (SOIC, 8-Leads, Body 4.9x3.9mm, Pitch 1.27mm, IPC High Density)
footprint SOIC-OA8_M (SOIC, 8-Leads, Body 4.9x3.9mm, Pitch 1.27mm, IPC Low Density)
pins: 1 VOUT (power), 2 GND (power), 3 NC, 4 BYPASS, 5 ~{SHDN} (in), 6 NC, 7 NC, 8 VIN (power)

## TC1107-2.8VUA
designator U?
300mA CMOS LDO with Shutdown and VREF Bypass, 8-Pin MSOP, Extended Temperature
footprint MSOP-UA8_N (TSOP, 8-Leads, Body 3x3mm, Pitch 0.65mm, IPC Medium Density)
footprint MSOP-UA8_L (TSOP, 8-Leads, Body 3x3mm, Pitch 0.65mm, IPC High Density)
footprint MSOP-UA8_M (TSOP, 8-Leads, Body 3x3mm, Pitch 0.65mm, IPC Low Density)
pins: 1 VOUT (power), 2 GND (power), 3 NC, 4 BYPASS, 5 ~{SHDN} (in), 6 NC, 7 NC, 8 VIN (power)

## TC1107-2.8VUATR
designator U?
300mA CMOS LDO with Shutdown and VREF Bypass, 8-Pin MSOP, Extended Temperature, Tape and Reel
footprint MSOP-UA8_N (TSOP, 8-Leads, Body 3x3mm, Pitch 0.65mm, IPC Medium Density)
footprint MSOP-UA8_L (TSOP, 8-Leads, Body 3x3mm, Pitch 0.65mm, IPC High Density)
footprint MSOP-UA8_M (TSOP, 8-Leads, Body 3x3mm, Pitch 0.65mm, IPC Low Density)
pins: 1 VOUT (power), 2 GND (power), 3 NC, 4 BYPASS, 5 ~{SHDN} (in), 6 NC, 7 NC, 8 VIN (power)

## TC1107-3.0VOA
designator U?
300mA CMOS LDO with Shutdown and VREF Bypass, 8-Pin SOIC 150mil, Extended Temperature
footprint SOIC-OA8_N (SOIC, 8-Leads, Body 4.9x3.9mm, Pitch 1.27mm, IPC Medium Density)
footprint SOIC-OA8_L (SOIC, 8-Leads, Body 4.9x3.9mm, Pitch 1.27mm, IPC High Density)
footprint SOIC-OA8_M (SOIC, 8-Leads, Body 4.9x3.9mm, Pitch 1.27mm, IPC Low Density)
pins: 1 VOUT (power), 2 GND (power), 3 NC, 4 BYPASS, 5 ~{SHDN} (in), 6 NC, 7 NC, 8 VIN (power)

## TC1107-3.0VOATR
designator U?
300mA CMOS LDO with Shutdown and VREF Bypass, 8-Pin SOIC 150mil, Extended Temperature, Tape and Reel
footprint SOIC-OA8_N (SOIC, 8-Leads, Body 4.9x3.9mm, Pitch 1.27mm, IPC Medium Density)
footprint SOIC-OA8_L (SOIC, 8-Leads, Body 4.9x3.9mm, Pitch 1.27mm, IPC High Density)
footprint SOIC-OA8_M (SOIC, 8-Leads, Body 4.9x3.9mm, Pitch 1.27mm, IPC Low Density)
pins: 1 VOUT (power), 2 GND (power), 3 NC, 4 BYPASS, 5 ~{SHDN} (in), 6 NC, 7 NC, 8 VIN (power)

## TC1107-3.0VUA
designator U?
300mA CMOS LDO with Shutdown and VREF Bypass, 8-Pin MSOP, Extended Temperature
footprint MSOP-UA8_N (TSOP, 8-Leads, Body 3x3mm, Pitch 0.65mm, IPC Medium Density)
footprint MSOP-UA8_L (TSOP, 8-Leads, Body 3x3mm, Pitch 0.65mm, IPC High Density)
footprint MSOP-UA8_M (TSOP, 8-Leads, Body 3x3mm, Pitch 0.65mm, IPC Low Density)
pins: 1 VOUT (power), 2 GND (power), 3 NC, 4 BYPASS, 5 ~{SHDN} (in), 6 NC, 7 NC, 8 VIN (power)

## TC1107-3.0VUATR
designator U?
300mA CMOS LDO with Shutdown and VREF Bypass, 8-Pin MSOP, Extended Temperature, Tape and Reel
footprint MSOP-UA8_N (TSOP, 8-Leads, Body 3x3mm, Pitch 0.65mm, IPC Medium Density)
footprint MSOP-UA8_L (TSOP, 8-Leads, Body 3x3mm, Pitch 0.65mm, IPC High Density)
footprint MSOP-UA8_M (TSOP, 8-Leads, Body 3x3mm, Pitch 0.65mm, IPC Low Density)
pins: 1 VOUT (power), 2 GND (power), 3 NC, 4 BYPASS, 5 ~{SHDN} (in), 6 NC, 7 NC, 8 VIN (power)

## TC1107-3.3VOA
designator U?
300mA CMOS LDO with Shutdown and VREF Bypass, 8-Pin SOIC 150mil, Extended Temperature
footprint SOIC-OA8_N (SOIC, 8-Leads, Body 4.9x3.9mm, Pitch 1.27mm, IPC Medium Density)
footprint SOIC-OA8_L (SOIC, 8-Leads, Body 4.9x3.9mm, Pitch 1.27mm, IPC High Density)
footprint SOIC-OA8_M (SOIC, 8-Leads, Body 4.9x3.9mm, Pitch 1.27mm, IPC Low Density)
pins: 1 VOUT (power), 2 GND (power), 3 NC, 4 BYPASS, 5 ~{SHDN} (in), 6 NC, 7 NC, 8 VIN (power)

## TC1107-3.3VOATR
designator U?
300mA CMOS LDO with Shutdown and VREF Bypass, 8-Pin SOIC 150mil, Extended Temperature, Tape and Reel
footprint SOIC-OA8_N (SOIC, 8-Leads, Body 4.9x3.9mm, Pitch 1.27mm, IPC Medium Density)
footprint SOIC-OA8_L (SOIC, 8-Leads, Body 4.9x3.9mm, Pitch 1.27mm, IPC High Density)
footprint SOIC-OA8_M (SOIC, 8-Leads, Body 4.9x3.9mm, Pitch 1.27mm, IPC Low Density)
pins: 1 VOUT (power), 2 GND (power), 3 NC, 4 BYPASS, 5 ~{SHDN} (in), 6 NC, 7 NC, 8 VIN (power)

## TC1107-3.3VUA
designator U?
300mA CMOS LDO with Shutdown and VREF Bypass, 8-Pin MSOP, Extended Temperature
footprint MSOP-UA8_N (TSOP, 8-Leads, Body 3x3mm, Pitch 0.65mm, IPC Medium Density)
footprint MSOP-UA8_L (TSOP, 8-Leads, Body 3x3mm, Pitch 0.65mm, IPC High Density)
footprint MSOP-UA8_M (TSOP, 8-Leads, Body 3x3mm, Pitch 0.65mm, IPC Low Density)
pins: 1 VOUT (power), 2 GND (power), 3 NC, 4 BYPASS, 5 ~{SHDN} (in), 6 NC, 7 NC, 8 VIN (power)

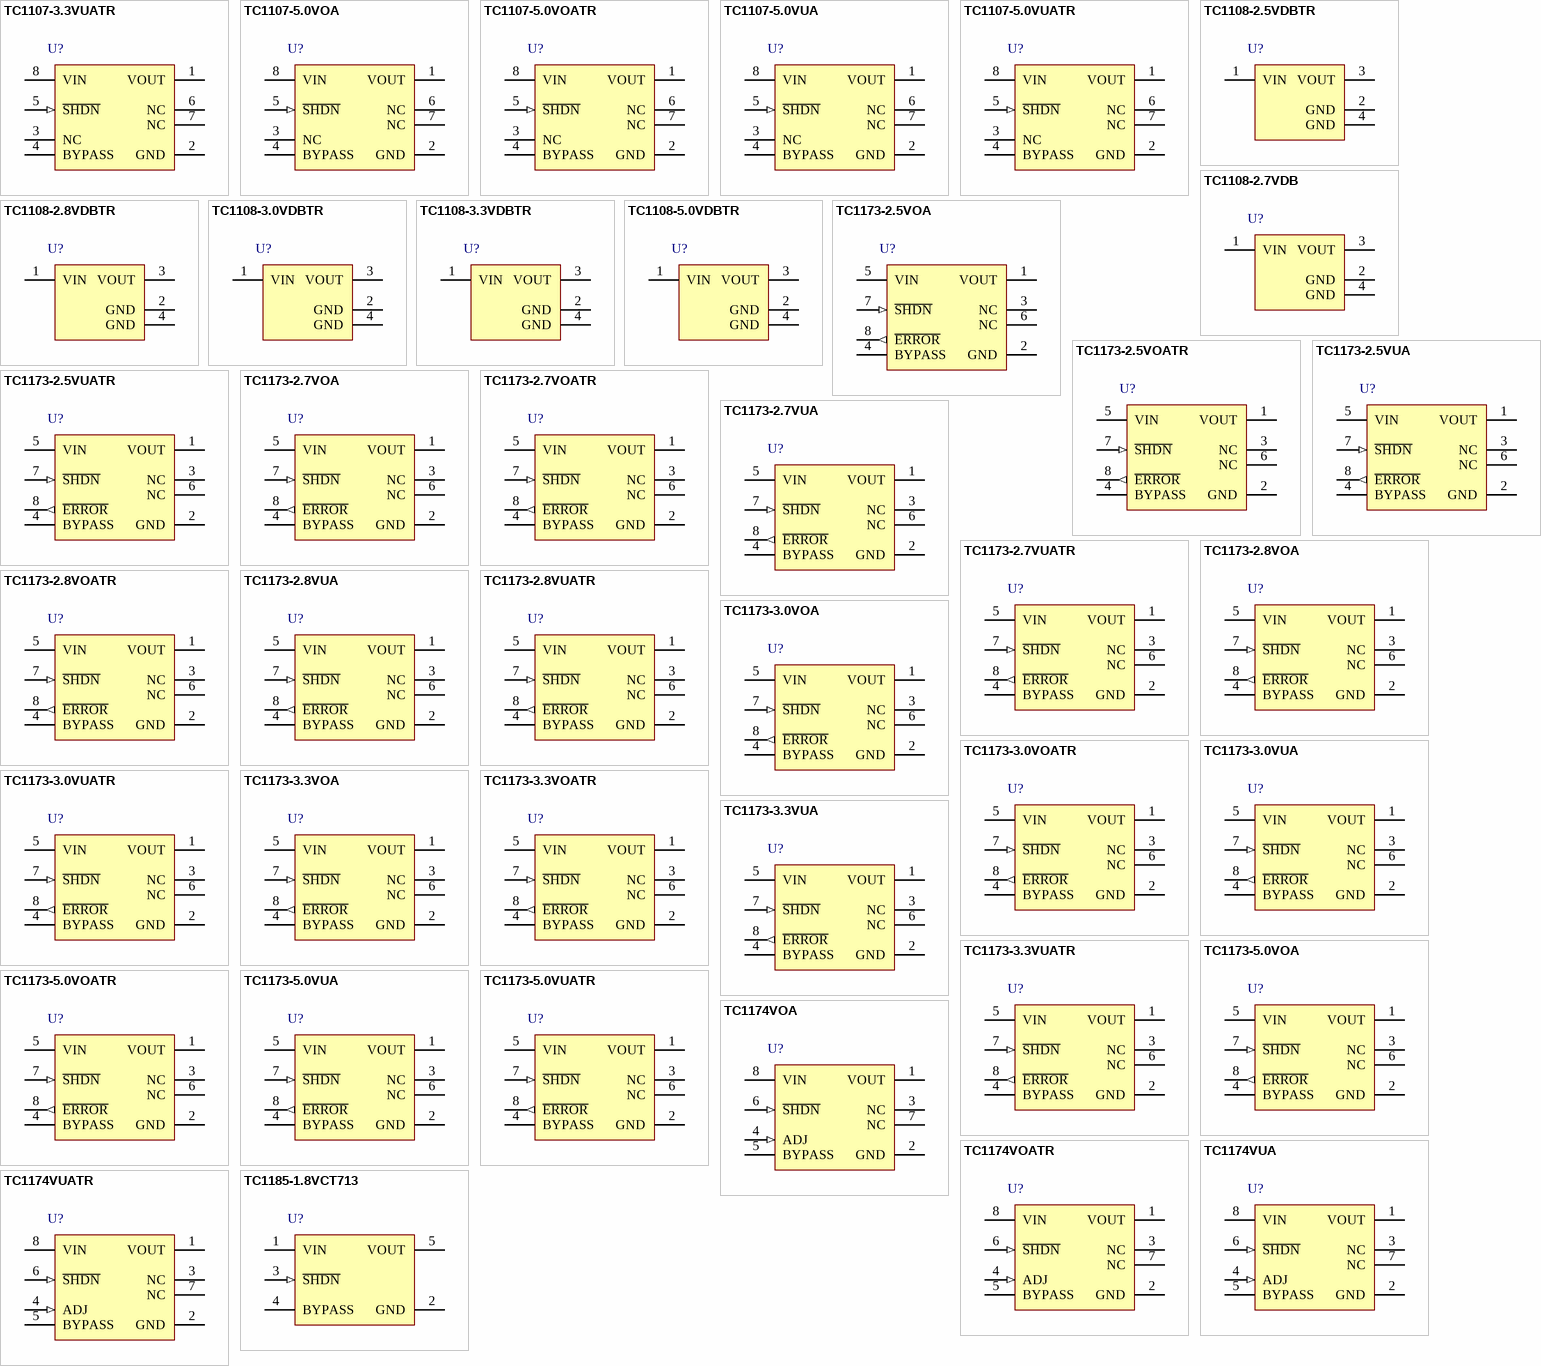
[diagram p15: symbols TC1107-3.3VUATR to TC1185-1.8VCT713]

## TC1107-3.3VUATR
designator U?
300mA CMOS LDO with Shutdown and VREF Bypass, 8-Pin MSOP, Extended Temperature, Tape and Reel
footprint MSOP-UA8_N (TSOP, 8-Leads, Body 3x3mm, Pitch 0.65mm, IPC Medium Density)
footprint MSOP-UA8_L (TSOP, 8-Leads, Body 3x3mm, Pitch 0.65mm, IPC High Density)
footprint MSOP-UA8_M (TSOP, 8-Leads, Body 3x3mm, Pitch 0.65mm, IPC Low Density)
pins: 1 VOUT (power), 2 GND (power), 3 NC, 4 BYPASS, 5 ~{SHDN} (in), 6 NC, 7 NC, 8 VIN (power)

## TC1107-5.0VOA
designator U?
300mA CMOS LDO with Shutdown and VREF Bypass, 8-Pin SOIC 150mil, Extended Temperature
footprint SOIC-OA8_N (SOIC, 8-Leads, Body 4.9x3.9mm, Pitch 1.27mm, IPC Medium Density)
footprint SOIC-OA8_L (SOIC, 8-Leads, Body 4.9x3.9mm, Pitch 1.27mm, IPC High Density)
footprint SOIC-OA8_M (SOIC, 8-Leads, Body 4.9x3.9mm, Pitch 1.27mm, IPC Low Density)
pins: 1 VOUT (power), 2 GND (power), 3 NC, 4 BYPASS, 5 ~{SHDN} (in), 6 NC, 7 NC, 8 VIN (power)

## TC1107-5.0VOATR
designator U?
300mA CMOS LDO with Shutdown and VREF Bypass, 8-Pin SOIC 150mil, Extended Temperature, Tape and Reel
footprint SOIC-OA8_N (SOIC, 8-Leads, Body 4.9x3.9mm, Pitch 1.27mm, IPC Medium Density)
footprint SOIC-OA8_L (SOIC, 8-Leads, Body 4.9x3.9mm, Pitch 1.27mm, IPC High Density)
footprint SOIC-OA8_M (SOIC, 8-Leads, Body 4.9x3.9mm, Pitch 1.27mm, IPC Low Density)
pins: 1 VOUT (power), 2 GND (power), 3 NC, 4 BYPASS, 5 ~{SHDN} (in), 6 NC, 7 NC, 8 VIN (power)

## TC1107-5.0VUA
designator U?
300mA CMOS LDO with Shutdown and VREF Bypass, 8-Pin MSOP, Extended Temperature
footprint MSOP-UA8_N (TSOP, 8-Leads, Body 3x3mm, Pitch 0.65mm, IPC Medium Density)
footprint MSOP-UA8_L (TSOP, 8-Leads, Body 3x3mm, Pitch 0.65mm, IPC High Density)
footprint MSOP-UA8_M (TSOP, 8-Leads, Body 3x3mm, Pitch 0.65mm, IPC Low Density)
pins: 1 VOUT (power), 2 GND (power), 3 NC, 4 BYPASS, 5 ~{SHDN} (in), 6 NC, 7 NC, 8 VIN (power)

## TC1107-5.0VUATR
designator U?
300mA CMOS LDO with Shutdown and VREF Bypass, 8-Pin MSOP, Extended Temperature, Tape and Reel
footprint MSOP-UA8_N (TSOP, 8-Leads, Body 3x3mm, Pitch 0.65mm, IPC Medium Density)
footprint MSOP-UA8_L (TSOP, 8-Leads, Body 3x3mm, Pitch 0.65mm, IPC High Density)
footprint MSOP-UA8_M (TSOP, 8-Leads, Body 3x3mm, Pitch 0.65mm, IPC Low Density)
pins: 1 VOUT (power), 2 GND (power), 3 NC, 4 BYPASS, 5 ~{SHDN} (in), 6 NC, 7 NC, 8 VIN (power)

## TC1108-2.5VDBTR
designator U?
300mA CMOS LDO, 3-Pin SOT-223, Extended Temperature, Tape and Reel
footprint SOT-223-DB3_N (SOT223, 4-Leads, Body 6.5x3.5mm, Pitch 2.3mm, Lead Span 7mm, IPC Medium Density)
footprint SOT-223-DB3_L (SOT223, 4-Leads, Body 6.5x3.5mm, Pitch 2.3mm, Lead Span 7mm, IPC High Density)
footprint SOT-223-DB3_M (SOT223, 4-Leads, Body 6.5x3.5mm, Pitch 2.3mm, Lead Span 7mm, IPC Low Density)
pins: 1 VIN (power), 2 GND (power), 3 VOUT (power), 4 GND (power)

## TC1108-2.7VDB
designator U?
300mA CMOS LDO, 3-Pin SOT-223, Extended Temperature
footprint SOT-223-DB3_N (SOT223, 4-Leads, Body 6.5x3.5mm, Pitch 2.3mm, Lead Span 7mm, IPC Medium Density)
footprint SOT-223-DB3_L (SOT223, 4-Leads, Body 6.5x3.5mm, Pitch 2.3mm, Lead Span 7mm, IPC High Density)
footprint SOT-223-DB3_M (SOT223, 4-Leads, Body 6.5x3.5mm, Pitch 2.3mm, Lead Span 7mm, IPC Low Density)
pins: 1 VIN (power), 2 GND (power), 3 VOUT (power), 4 GND (power)

## TC1108-2.8VDBTR
designator U?
300mA CMOS LDO, 3-Pin SOT-223, Extended Temperature, Tape and Reel
footprint SOT-223-DB3_N (SOT223, 4-Leads, Body 6.5x3.5mm, Pitch 2.3mm, Lead Span 7mm, IPC Medium Density)
footprint SOT-223-DB3_L (SOT223, 4-Leads, Body 6.5x3.5mm, Pitch 2.3mm, Lead Span 7mm, IPC High Density)
footprint SOT-223-DB3_M (SOT223, 4-Leads, Body 6.5x3.5mm, Pitch 2.3mm, Lead Span 7mm, IPC Low Density)
pins: 1 VIN (power), 2 GND (power), 3 VOUT (power), 4 GND (power)

## TC1108-3.0VDBTR
designator U?
300mA CMOS LDO, 3-Pin SOT-223, Extended Temperature, Tape and Reel
footprint SOT-223-DB3_N (SOT223, 4-Leads, Body 6.5x3.5mm, Pitch 2.3mm, Lead Span 7mm, IPC Medium Density)
footprint SOT-223-DB3_L (SOT223, 4-Leads, Body 6.5x3.5mm, Pitch 2.3mm, Lead Span 7mm, IPC High Density)
footprint SOT-223-DB3_M (SOT223, 4-Leads, Body 6.5x3.5mm, Pitch 2.3mm, Lead Span 7mm, IPC Low Density)
pins: 1 VIN (power), 2 GND (power), 3 VOUT (power), 4 GND (power)

## TC1108-3.3VDBTR
designator U?
300mA CMOS LDO, 3-Pin SOT-223, Extended Temperature, Tape and Reel
footprint SOT-223-DB3_N (SOT223, 4-Leads, Body 6.5x3.5mm, Pitch 2.3mm, Lead Span 7mm, IPC Medium Density)
footprint SOT-223-DB3_L (SOT223, 4-Leads, Body 6.5x3.5mm, Pitch 2.3mm, Lead Span 7mm, IPC High Density)
footprint SOT-223-DB3_M (SOT223, 4-Leads, Body 6.5x3.5mm, Pitch 2.3mm, Lead Span 7mm, IPC Low Density)
pins: 1 VIN (power), 2 GND (power), 3 VOUT (power), 4 GND (power)

## TC1108-5.0VDBTR
designator U?
300mA CMOS LDO, 3-Pin SOT-223, Extended Temperature, Tape and Reel
footprint SOT-223-DB3_N (SOT223, 4-Leads, Body 6.5x3.5mm, Pitch 2.3mm, Lead Span 7mm, IPC Medium Density)
footprint SOT-223-DB3_L (SOT223, 4-Leads, Body 6.5x3.5mm, Pitch 2.3mm, Lead Span 7mm, IPC High Density)
footprint SOT-223-DB3_M (SOT223, 4-Leads, Body 6.5x3.5mm, Pitch 2.3mm, Lead Span 7mm, IPC Low Density)
pins: 1 VIN (power), 2 GND (power), 3 VOUT (power), 4 GND (power)

## TC1173-2.5VOA
designator U?
300mA CMOS LDO with Shutdown Active-Low Error Output and Bypass, 8-Pin SOIC 150mil, Extended Temperature
footprint SOIC-OA8_N (SOIC, 8-Leads, Body 4.9x3.9mm, Pitch 1.27mm, IPC Medium Density)
footprint SOIC-OA8_L (SOIC, 8-Leads, Body 4.9x3.9mm, Pitch 1.27mm, IPC High Density)
footprint SOIC-OA8_M (SOIC, 8-Leads, Body 4.9x3.9mm, Pitch 1.27mm, IPC Low Density)
pins: 1 VOUT (power), 2 GND (power), 3 NC, 4 BYPASS, 5 VIN (power), 6 NC, 7 ~{SHDN} (in), 8 ~{ERROR} (out)

## TC1173-2.5VOATR
designator U?
300mA CMOS LDO with Shutdown Active-Low Error Output and Bypass, 8-Pin SOIC 150mil, Extended Temperature, Tape and Reel
footprint SOIC-OA8_N (SOIC, 8-Leads, Body 4.9x3.9mm, Pitch 1.27mm, IPC Medium Density)
footprint SOIC-OA8_L (SOIC, 8-Leads, Body 4.9x3.9mm, Pitch 1.27mm, IPC High Density)
footprint SOIC-OA8_M (SOIC, 8-Leads, Body 4.9x3.9mm, Pitch 1.27mm, IPC Low Density)
pins: 1 VOUT (power), 2 GND (power), 3 NC, 4 BYPASS, 5 VIN (power), 6 NC, 7 ~{SHDN} (in), 8 ~{ERROR} (out)

## TC1173-2.5VUA
designator U?
300mA CMOS LDO with Shutdown Active-Low Error Output and Bypass, 8-Pin MSOP, Extended Temperature
footprint MSOP-UA8_N (TSOP, 8-Leads, Body 3x3mm, Pitch 0.65mm, IPC Medium Density)
footprint MSOP-UA8_L (TSOP, 8-Leads, Body 3x3mm, Pitch 0.65mm, IPC High Density)
footprint MSOP-UA8_M (TSOP, 8-Leads, Body 3x3mm, Pitch 0.65mm, IPC Low Density)
pins: 1 VOUT (power), 2 GND (power), 3 NC, 4 BYPASS, 5 VIN (power), 6 NC, 7 ~{SHDN} (in), 8 ~{ERROR} (out)

## TC1173-2.5VUATR
designator U?
300mA CMOS LDO with Shutdown Active-Low Error Output and Bypass, 8-Pin MSOP, Extended Temperature, Tape and Reel
footprint MSOP-UA8_N (TSOP, 8-Leads, Body 3x3mm, Pitch 0.65mm, IPC Medium Density)
footprint MSOP-UA8_L (TSOP, 8-Leads, Body 3x3mm, Pitch 0.65mm, IPC High Density)
footprint MSOP-UA8_M (TSOP, 8-Leads, Body 3x3mm, Pitch 0.65mm, IPC Low Density)
pins: 1 VOUT (power), 2 GND (power), 3 NC, 4 BYPASS, 5 VIN (power), 6 NC, 7 ~{SHDN} (in), 8 ~{ERROR} (out)

## TC1173-2.7VOA
designator U?
300mA CMOS LDO with Shutdown Active-Low Error Output and Bypass, 8-Pin SOIC 150mil, Extended Temperature
footprint SOIC-OA8_N (SOIC, 8-Leads, Body 4.9x3.9mm, Pitch 1.27mm, IPC Medium Density)
footprint SOIC-OA8_L (SOIC, 8-Leads, Body 4.9x3.9mm, Pitch 1.27mm, IPC High Density)
footprint SOIC-OA8_M (SOIC, 8-Leads, Body 4.9x3.9mm, Pitch 1.27mm, IPC Low Density)
pins: 1 VOUT (power), 2 GND (power), 3 NC, 4 BYPASS, 5 VIN (power), 6 NC, 7 ~{SHDN} (in), 8 ~{ERROR} (out)

## TC1173-2.7VOATR
designator U?
300mA CMOS LDO with Shutdown Active-Low Error Output and Bypass, 8-Pin SOIC 150mil, Extended Temperature, Tape and Reel
footprint SOIC-OA8_N (SOIC, 8-Leads, Body 4.9x3.9mm, Pitch 1.27mm, IPC Medium Density)
footprint SOIC-OA8_L (SOIC, 8-Leads, Body 4.9x3.9mm, Pitch 1.27mm, IPC High Density)
footprint SOIC-OA8_M (SOIC, 8-Leads, Body 4.9x3.9mm, Pitch 1.27mm, IPC Low Density)
pins: 1 VOUT (power), 2 GND (power), 3 NC, 4 BYPASS, 5 VIN (power), 6 NC, 7 ~{SHDN} (in), 8 ~{ERROR} (out)

## TC1173-2.7VUA
designator U?
300mA CMOS LDO with Shutdown Active-Low Error Output and Bypass, 8-Pin MSOP, Extended Temperature
footprint MSOP-UA8_N (TSOP, 8-Leads, Body 3x3mm, Pitch 0.65mm, IPC Medium Density)
footprint MSOP-UA8_L (TSOP, 8-Leads, Body 3x3mm, Pitch 0.65mm, IPC High Density)
footprint MSOP-UA8_M (TSOP, 8-Leads, Body 3x3mm, Pitch 0.65mm, IPC Low Density)
pins: 1 VOUT (power), 2 GND (power), 3 NC, 4 BYPASS, 5 VIN (power), 6 NC, 7 ~{SHDN} (in), 8 ~{ERROR} (out)

## TC1173-2.7VUATR
designator U?
300mA CMOS LDO with Shutdown Active-Low Error Output and Bypass, 8-Pin MSOP, Extended Temperature, Tape and Reel
footprint MSOP-UA8_N (TSOP, 8-Leads, Body 3x3mm, Pitch 0.65mm, IPC Medium Density)
footprint MSOP-UA8_L (TSOP, 8-Leads, Body 3x3mm, Pitch 0.65mm, IPC High Density)
footprint MSOP-UA8_M (TSOP, 8-Leads, Body 3x3mm, Pitch 0.65mm, IPC Low Density)
pins: 1 VOUT (power), 2 GND (power), 3 NC, 4 BYPASS, 5 VIN (power), 6 NC, 7 ~{SHDN} (in), 8 ~{ERROR} (out)

## TC1173-2.8VOA
designator U?
300mA CMOS LDO with Shutdown Active-Low Error Output and Bypass, 8-Pin SOIC 150mil, Extended Temperature
footprint SOIC-OA8_N (SOIC, 8-Leads, Body 4.9x3.9mm, Pitch 1.27mm, IPC Medium Density)
footprint SOIC-OA8_L (SOIC, 8-Leads, Body 4.9x3.9mm, Pitch 1.27mm, IPC High Density)
footprint SOIC-OA8_M (SOIC, 8-Leads, Body 4.9x3.9mm, Pitch 1.27mm, IPC Low Density)
pins: 1 VOUT (power), 2 GND (power), 3 NC, 4 BYPASS, 5 VIN (power), 6 NC, 7 ~{SHDN} (in), 8 ~{ERROR} (out)

## TC1173-2.8VOATR
designator U?
300mA CMOS LDO with Shutdown Active-Low Error Output and Bypass, 8-Pin SOIC 150mil, Extended Temperature, Tape and Reel
footprint SOIC-OA8_N (SOIC, 8-Leads, Body 4.9x3.9mm, Pitch 1.27mm, IPC Medium Density)
footprint SOIC-OA8_L (SOIC, 8-Leads, Body 4.9x3.9mm, Pitch 1.27mm, IPC High Density)
footprint SOIC-OA8_M (SOIC, 8-Leads, Body 4.9x3.9mm, Pitch 1.27mm, IPC Low Density)
pins: 1 VOUT (power), 2 GND (power), 3 NC, 4 BYPASS, 5 VIN (power), 6 NC, 7 ~{SHDN} (in), 8 ~{ERROR} (out)

## TC1173-2.8VUA
designator U?
300mA CMOS LDO with Shutdown Active-Low Error Output and Bypass, 8-Pin MSOP, Extended Temperature
footprint MSOP-UA8_N (TSOP, 8-Leads, Body 3x3mm, Pitch 0.65mm, IPC Medium Density)
footprint MSOP-UA8_L (TSOP, 8-Leads, Body 3x3mm, Pitch 0.65mm, IPC High Density)
footprint MSOP-UA8_M (TSOP, 8-Leads, Body 3x3mm, Pitch 0.65mm, IPC Low Density)
pins: 1 VOUT (power), 2 GND (power), 3 NC, 4 BYPASS, 5 VIN (power), 6 NC, 7 ~{SHDN} (in), 8 ~{ERROR} (out)

## TC1173-2.8VUATR
designator U?
300mA CMOS LDO with Shutdown Active-Low Error Output and Bypass, 8-Pin MSOP, Extended Temperature, Tape and Reel
footprint MSOP-UA8_N (TSOP, 8-Leads, Body 3x3mm, Pitch 0.65mm, IPC Medium Density)
footprint MSOP-UA8_L (TSOP, 8-Leads, Body 3x3mm, Pitch 0.65mm, IPC High Density)
footprint MSOP-UA8_M (TSOP, 8-Leads, Body 3x3mm, Pitch 0.65mm, IPC Low Density)
pins: 1 VOUT (power), 2 GND (power), 3 NC, 4 BYPASS, 5 VIN (power), 6 NC, 7 ~{SHDN} (in), 8 ~{ERROR} (out)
